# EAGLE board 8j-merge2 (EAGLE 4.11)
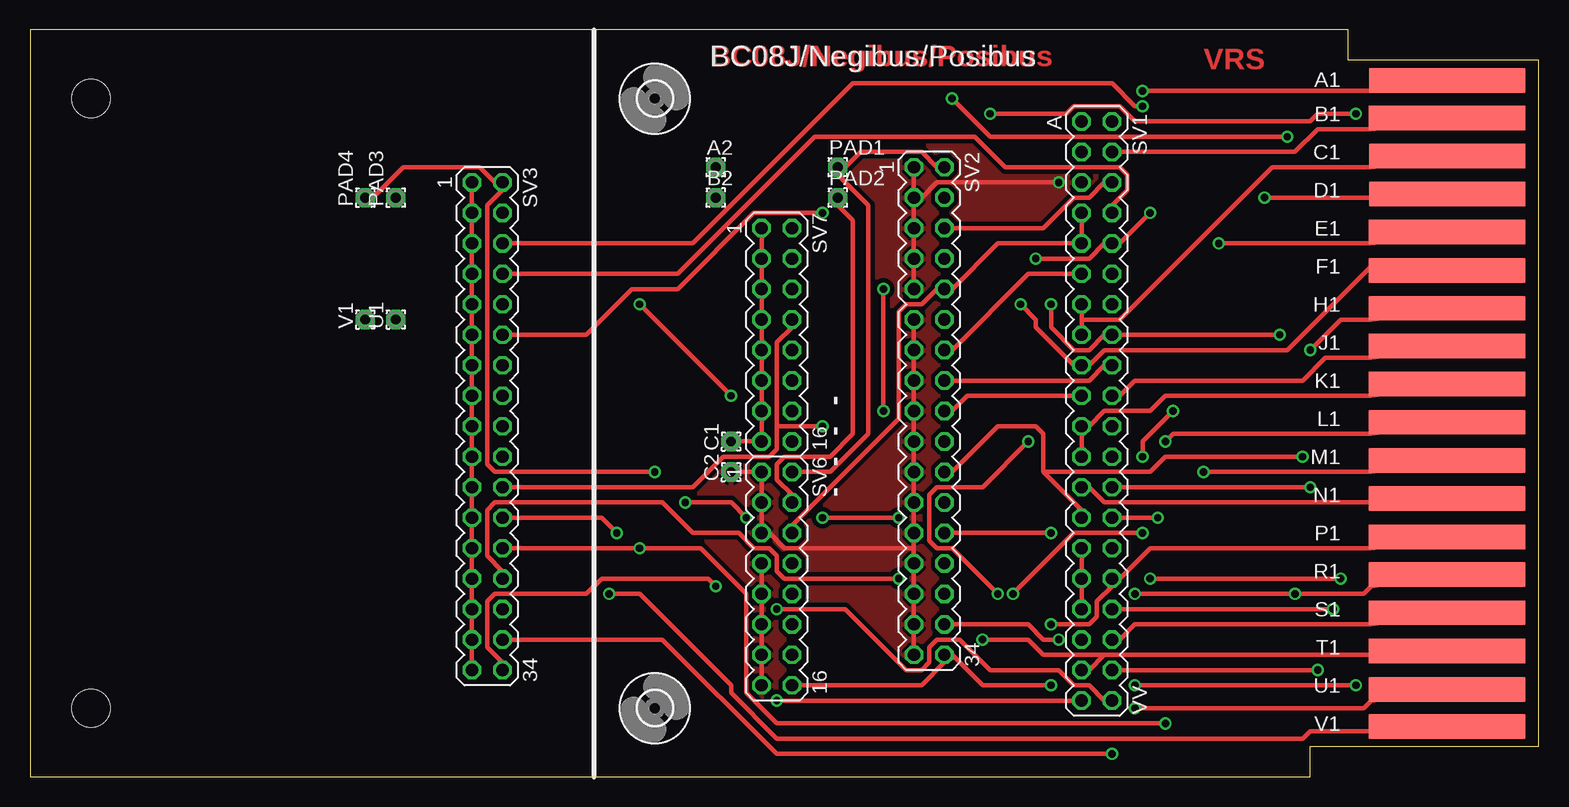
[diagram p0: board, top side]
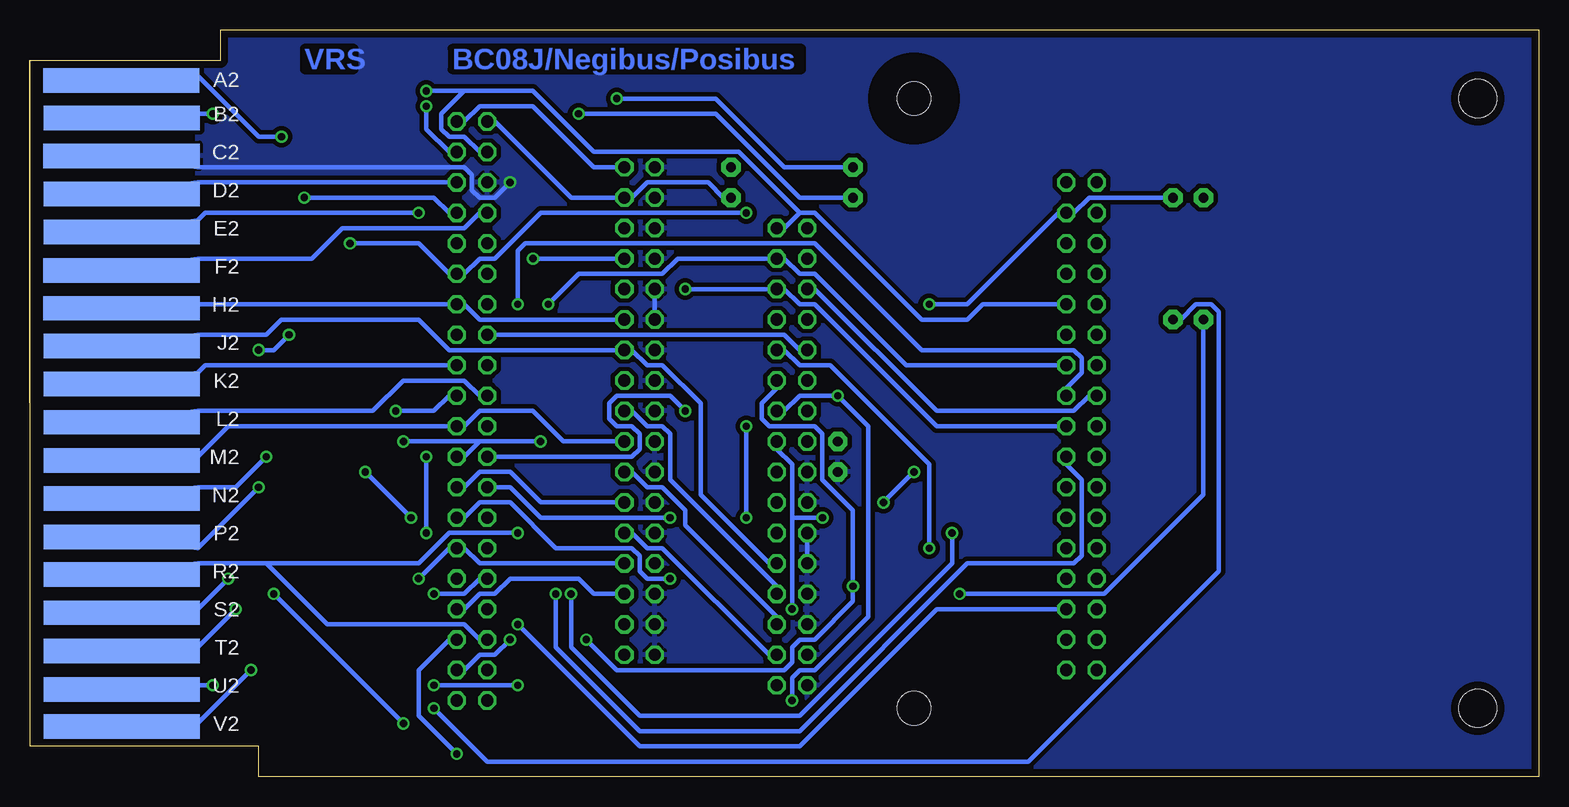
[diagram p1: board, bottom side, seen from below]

Size 125.73 x 62.23 mm. Coordinates in mm from the lower left corner, seen from the top.
Copper layers (1*16): Top 0.035mm / dielectric 1.5mm / Bottom 0.035mm
Design rules "olimex10mil": minimum track width 15mil, minimum drill 24mil, track to track 15mil, track to pad 10mil, pad to pad 10mil, via to via 10mil, smd to smd 10mil, copper to edge 25mil, drill to drill 10mil, minimum pad ring 10mil, minimum via ring 8mil, stop-mask expansion 0mil, vias tented up to drill 0mil, thermal gap 10mil

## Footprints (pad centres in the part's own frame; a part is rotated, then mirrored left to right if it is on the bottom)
1,6/0,8 = drill 0.813 pad 1.6 octagon: 1 0,0
DEC40PINV = drill 1.016 octagon: A -24.13,-1.27; AA 3.81,-1.27; B -24.13,1.27; BB 3.81,1.27; C -21.59,-1.27; CC 6.35,-1.27; D -21.59,1.27; DD 6.35,1.27; E -19.05,-1.27; EE 8.89,-1.27; F -19.05,1.27; FF 8.89,1.27; H -16.51,-1.27; HH 11.43,-1.27; J -16.51,1.27; JJ 11.43,1.27; K -13.97,-1.27; KK 13.97,-1.27; L -13.97,1.27; LL 13.97,1.27; M -11.43,-1.27; MM 16.51,-1.27; N -11.43,1.27; NN 16.51,1.27; P -8.89,-1.27; PP 19.05,-1.27; R -8.89,1.27; RR 19.05,1.27; S -6.35,-1.27; SS 21.59,-1.27; T -6.35,1.27; TT 21.59,1.27; U -3.81,-1.27; UU 24.13,-1.27; V -3.81,1.27; VV 24.13,1.27; W -1.27,-1.27; X -1.27,1.27; Y 1.27,-1.27; Z 1.27,1.27
MA17-2 = drill 1.016 octagon: 1 -20.32,-1.27; 2 -20.32,1.27; 3 -17.78,-1.27; 4 -17.78,1.27; 5 -15.24,-1.27; 6 -15.24,1.27; 7 -12.7,-1.27; 8 -12.7,1.27; 9 -10.16,-1.27; 10 -10.16,1.27; 11 -7.62,-1.27; 12 -7.62,1.27; 13 -5.08,-1.27; 14 -5.08,1.27; 15 -2.54,-1.27; 16 -2.54,1.27; 17 0,-1.27; 18 0,1.27; 19 2.54,-1.27; 20 2.54,1.27; 21 5.08,-1.27; 22 5.08,1.27; 23 7.62,-1.27; 24 7.62,1.27; 25 10.16,-1.27; 26 10.16,1.27; 27 12.7,-1.27; 28 12.7,1.27; 29 15.24,-1.27; 30 15.24,1.27; 31 17.78,-1.27; 32 17.78,1.27; 33 20.32,-1.27; 34 20.32,1.27
MA08-2 = drill 1.016 octagon: 1 -8.89,-1.27; 2 -8.89,1.27; 3 -6.35,-1.27; 4 -6.35,1.27; 5 -3.81,-1.27; 6 -3.81,1.27; 7 -1.27,-1.27; 8 -1.27,1.27; 9 1.27,-1.27; 10 1.27,1.27; 11 3.81,-1.27; 12 3.81,1.27; 13 6.35,-1.27; 14 6.35,1.27; 15 8.89,-1.27; 16 8.89,1.27
SINGLE-R = hole 3.175: 5.08,5.715; 5.08,56.515
EDGE-CON2 = smd 13.017 x 2.032: A1 7.633,4.207; B1 7.639,7.327; C1 7.636,10.489; D1 7.633,13.665; E1 7.642,16.84; F1 7.642,20.041; H1 7.642,23.19; J1 7.642,26.34; K1 7.642,29.515; L1 7.642,32.69; M1 7.642,35.89; N1 7.642,39.04; P1 7.642,42.24; R1 7.642,45.39; S1 7.642,48.565; T1 7.642,51.74; U1 7.642,54.966; V1 7.642,58.026 | smd 13.017 x 2.032 bottom: A2 7.614,4.207; B2 7.642,7.328; C2 7.617,10.49; D2 7.642,13.665; E2 7.642,16.84; F2 7.617,20.041; H2 7.617,23.19; J2 7.642,26.34; K2 7.642,29.515; L2 7.642,32.69; M2 7.642,35.89; N2 7.642,39.04; P2 7.642,42.24; R2 7.642,45.39; S2 7.642,48.565; T2 7.642,51.74; U2 7.642,54.966; V2 7.642,58.026
2,8 = hole 2.8: 0,0

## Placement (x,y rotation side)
A2  [1,6/0,8]  57.15,50.8 0 top
B2  [1,6/0,8]  57.15,48.26 0 top
C1  [1,6/0,8]  58.42,27.94 90 top
C2  [1,6/0,8]  58.42,25.4 90 top
PAD1  [1,6/0,8]  67.31,50.8 0 top
PAD2  [1,6/0,8]  67.31,48.26 0 top
PAD3  [1,6/0,8]  30.48,48.26 90 top
PAD4  [1,6/0,8]  27.94,48.26 90 top
SV1  [DEC40PINV]  88.9,30.48 270 top
SV2  [MA17-2]  74.93,30.48 270 top
SV3  [MA17-2]  38.1,29.21 270 top
SV6  [MA08-2]  62.23,16.51 270 top
SV7  [MA08-2]  62.23,36.83 270 top
U1  [1,6/0,8]  30.48,38.1 90 top
U$1  OUTLINE-SINGLE-R  [SINGLE-R]  0,0 0 top
U$2  [EDGE-CON2]  125.73,62.23 180 top
U$3  [2,8]  52.07,56.52 0 top
U$4  [2,8]  52.07,5.71 0 top
V1  [1,6/0,8]  27.94,38.1 90 top

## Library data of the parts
A2 B2 C1 C2 PAD1-PAD4 U1 V1 = wirepad
SV1 U$1 U$2 = dec-con
SV2 SV3 SV6 SV7 = con-lstb
U$3 U$4 = holes

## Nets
-15V: B2.1 U$2.B2
A1: SV1.C SV3.10 SV7.2 U$2.A1
B1: SV1.D SV3.6 U$2.B1
C1: C1.1 SV1.P SV1.S SV3.1 SV3.3 SV3.5 SV3.7 SV3.9 SV3.11 SV3.13 SV3.15 SV3.17 SV3.19 SV3.21 SV3.23 SV3.25 SV3.27 SV3.29 SV3.31 SV3.33 SV7.1 SV7.3 SV7.5 SV7.7 SV7.9 SV7.11 SV7.13 SV7.15 U$2.C1
C2: C2.1 SV1.E SV2.1 SV2.3 SV2.5 SV2.7 SV2.9 SV2.11 SV2.13 SV2.15 SV2.17 SV2.19 SV2.21 SV2.23 SV2.25 SV2.27 SV2.29 SV2.31 SV2.33 SV6.1 SV6.3 SV6.5 SV6.7 SV6.9 SV6.11 SV6.13 SV6.15 U$2.C2
D1: SV1.J SV3.8 U$2.D1
D2: SV1.F SV2.6 U$2.D2
E1: SV1.N SV3.12 U$2.E1
E2: SV1.L SV2.8 U$2.E2
F1: SV1.U SV3.14 SV7.4 U$2.F1
F2: SV1.H SV1.K SV2.10 SV6.6 U$2.F2
H1: SV1.T SV3.16 U$2.H1
H2: SV1.R SV2.12 U$2.H2
J1: SV1.X SV3.20 U$2.J1
J2: SV1.M SV2.14 SV6.8 U$2.J2
JA2: PAD1.1 SV1.B SV2.2 SV6.2
JB2: PAD2.1 SV1.A SV2.4 SV6.4
JU1: PAD3.1 SV1.UU SV3.4 SV7.14
JV1: PAD4.1 SV1.VV SV3.2 SV7.16
K1: SV1.AA SV1.Y SV3.18 SV7.6 U$2.K1
K2: SV1.V SV2.16 U$2.K2
L1: SV1.BB SV3.24 U$2.L1
L2: SV1.W SV2.18 SV6.10 U$2.L2
M1: SV1.FF SV3.28 U$2.M1
M2: SV1.Z SV2.20 U$2.M2
N1: SV1.CC SV3.22 SV7.8 U$2.N1
N2: SV1.EE SV2.22 SV6.12 U$2.N2
P1: SV1.LL SV3.30 U$2.P1
P2: SV1.DD SV2.24 U$2.P2
R1: SV1.HH SV1.KK SV1.MM SV3.26 SV7.10 U$2.R1
R2: SV1.PP SV2.26 SV6.14 U$2.R2
S1: SV1.RR SV3.32 U$2.S1
S2: SV1.JJ SV2.28 U$2.S2
T1: SV1.SS SV3.34 SV7.12 U$2.T1
T2: SV1.NN SV2.30 U$2.T2
U1: U1.1 U$2.U1
U2: SV2.34 SV6.16 U$2.U2
V1: U$2.V1 V1.1
V2: SV1.TT SV2.32 U$2.V2
VCC: A2.1 U$2.A2

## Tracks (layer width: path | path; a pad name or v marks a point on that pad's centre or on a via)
-15V  (via drill 0.61)
  Top 0.381: v80.01,55.24 86.36,55.24 87,55.88 90.81,55.88 92.08,54.61 106.68,54.61 107.31,55.24 v110.49,55.24
  Bottom 0.381: v80.01,55.24 68.58,55.24 61.59,48.26 57.78,48.26 B2.1 | v110.49,55.24 111.76,55.24 U$2.B2
A1  (via drill 0.61)
  Top 0.381: v92.71,57.15 111.76,57.15 U$2.A1
  Bottom 0.381: 61.59,46.99 60.33,46.99 51.44,38.1 47.62,38.1 46.35,39.37 40.01,39.37 SV3.10 | 61.59,46.99 62.87,45.72 SV7.2 | 89.53,57.15 91.44,55.24 91.44,53.98 90.81,53.34 89.53,53.34 88.27,52.07 SV1.C | 89.53,57.15 83.82,57.15 78.74,52.07 66.67,52.07 61.59,46.99 | 89.53,57.15 v92.71,57.15
B1  (via drill 0.61)
  Top 0.381: v92.71,55.88 92.08,55.88 90.17,57.78 68.58,57.78 55.24,44.45 40.01,44.45 SV3.6 | U$2.B1 111.76,53.98 107.31,53.98 105.41,52.07 90.81,52.07 SV1.D
  Bottom 0.381: v92.71,55.88 92.71,53.98 90.81,52.07 SV1.D
C1
  Top 0.381: SV3.33 36.83,9.53 36.83,10.79 SV3.31 36.83,12.06 36.83,13.34 SV3.29 36.83,14.61 36.83,15.88 SV3.27 36.83,17.14 36.83,18.41 SV3.25 36.83,19.68 36.83,20.95 SV3.23 36.83,22.23 36.83,23.5 SV3.21 36.83,24.77 36.83,26.04 SV3.19 36.83,27.3 36.83,28.57 SV3.17 36.83,29.84 36.83,31.11 SV3.15 36.83,32.38 36.83,33.66 SV3.13 36.83,34.92 36.83,36.2 SV3.11 36.83,37.47 36.83,38.73 SV3.9 36.83,40.01 36.83,41.27 SV3.7 36.83,42.55 36.83,43.81 SV3.5 36.83,45.09 36.83,46.35 SV3.3 36.83,47.62 36.83,48.9 SV3.1 | 87.63,38.1 87.63,38.73 SV1.P | 87.63,38.1 87.63,37.47 SV1.S | C1.1 59.05,27.94 60.33,27.94 SV7.15 60.96,28.57 60.96,29.84 SV7.13 60.96,31.11 60.96,32.38 SV7.11 60.96,33.66 60.96,34.92 SV7.9 60.96,36.2 60.96,37.47 SV7.7 60.96,38.73 60.96,40.01 SV7.5 60.96,41.27 60.96,42.55 SV7.3 60.96,43.81 60.96,45.09 SV7.1 | 87.63,38.1 90.81,38.1 103.5,50.8 111.76,50.8 U$2.C1
  Bottom 0.381: SV1.S 87,36.83 62.87,36.83 61.59,35.56 SV7.9 | SV3.15 37.47,31.75 38.73,30.48 50.16,30.48 60.33,40.64 SV7.5
C2  (via drill 0.61)
  Top 0.381: SV6.15 60.96,8.26 60.96,9.53 SV6.13 60.96,10.79 60.96,12.06 SV6.11 60.96,13.34 60.96,14.61 SV6.9 60.96,15.88 60.96,17.14 SV6.7 | C2.1 59.05,25.4 60.33,25.4 SV6.1 60.96,24.77 60.96,23.5 SV6.3 60.96,22.23 60.96,20.95 SV6.5 61.59,20.32 62.87,19.05 73.66,19.05 | SV2.33 73.66,10.79 73.66,12.06 SV2.31 73.66,13.34 73.66,14.61 SV2.29 73.66,15.88 73.66,17.14 SV2.27 73.66,18.41 73.66,19.05 | 73.66,19.05 73.66,19.68 SV2.25 73.66,20.95 73.66,22.23 SV2.23 73.66,23.5 73.66,24.77 SV2.21 73.66,26.04 73.66,27.3 SV2.19 73.66,28.57 73.66,29.84 SV2.17 73.66,31.11 73.66,32.38 SV2.15 73.66,33.66 73.66,34.92 SV2.13 73.66,36.2 73.66,37.47 SV2.11 | SV2.9 73.66,41.27 73.66,42.55 SV2.7 73.66,43.81 73.66,45.09 SV2.5 73.66,46.35 73.66,47.62 SV2.3 | SV2.1 73.66,50.16 73.66,48.9 SV2.3 | v85.72,49.53 75.56,49.53 74.3,48.26 SV2.3
  Bottom 0.381: SV6.5 60.96,19.68 60.96,18.41 SV6.7 | SV2.9 73.66,40.01 73.66,38.73 SV2.11 | v85.72,49.53 87,48.26 88.27,48.26 88.9,48.9 88.9,50.16 89.53,50.8 111.76,50.8 U$2.C2
  pour Bottom (isolate 0.254): 0,0 111.76,0 111.76,62.23 0,62.23
  pour Top (isolate 0.254): 0,0 111.76,0 111.76,62.23 0,62.23
D1  (via drill 0.61)
  Top 0.381: SV3.8 40.01,41.91 53.98,41.91 65.41,53.34 78.74,53.34 81.28,50.8 90.81,50.8 91.44,50.16 91.44,48.9 90.17,47.62 SV1.J | v102.87,48.26 111.76,48.26 U$2.D1
  Bottom 0.381: v102.87,48.26 92.08,48.26 90.81,46.99 SV1.J
D2
  Top 0.381: SV2.6 76.83,45.72 84.45,45.72 87,48.26 88.27,48.26 89.53,49.53 SV1.F
  Bottom 0.381: SV1.F 90.81,49.53 111.76,49.53 U$2.D2
E1  (via drill 0.61)
  Top 0.381: v66.04,46.99 60.33,46.99 53.98,40.64 50.16,40.64 46.35,36.83 40.01,36.83 SV3.12 | v99.06,44.45 111.76,44.45 U$2.E1
  Bottom 0.381: v66.04,46.99 83.19,46.99 87,43.18 88.27,43.18 89.53,41.91 SV1.N 90.81,41.91 93.34,44.45 v99.06,44.45
E2  (via drill 0.61)
  Top 0.381: v83.82,43.18 88.27,43.18 89.53,44.45 SV1.L 90.81,44.45 v93.34,46.99
  Bottom 0.381: v83.82,43.18 76.83,43.18 SV2.8 | v93.34,46.99 111.12,46.99 111.76,46.35 U$2.E2
F1  (via drill 0.61)
  Top 0.381: U$2.F1 111.76,42.55 104.78,35.56 89.53,35.56 88.27,34.29 SV1.U 87,34.29 83.82,37.47 83.82,38.1 v82.55,39.37
  Bottom 0.381: SV3.14 40.01,34.29 52.7,34.29 60.33,41.91 61.59,41.91 62.87,43.18 SV7.4 64.14,43.18 71.75,43.18 73.03,41.91 80.01,41.91 v82.55,39.37
F2
  Top 0.381: SV1.H 87.63,46.35 87.63,45.09 SV1.K 87,44.45 80.64,44.45 76.83,40.64 SV2.10 75.56,40.64 74.3,39.37 73.03,39.37 72.39,38.73 72.39,29.84 63.5,20.95 SV6.6
  Bottom 0.381: U$2.F2 111.76,43.18 102.23,43.18 99.69,45.72 89.53,45.72 88.27,46.99 SV1.H
H1  (via drill 0.61)
  Top 0.381: v85.09,39.37 85.09,37.47 87,35.56 88.27,35.56 89.53,36.83 SV1.T 90.81,36.83 v104.14,36.83 | v106.68,35.56 109.22,38.1 111.76,38.1 U$2.H1
  Bottom 0.381: v85.09,39.37 85.09,43.81 84.45,44.45 60.33,44.45 51.44,35.56 38.73,35.56 38.1,34.92 38.1,33.66 39.37,32.38 SV3.16 | v106.68,35.56 105.41,35.56 v104.14,36.83
H2
  Bottom 0.381: SV2.12 76.83,38.1 88.27,38.1 89.53,39.37 SV1.R 90.81,39.37 111.76,39.37 U$2.H2
J1  (via drill 0.61)
  Top 0.381: v81.92,15.24 87,20.32 v92.71,20.32 | v92.71,26.67 92.71,27.94 v95.25,30.48 | U$2.J1 111.76,34.92 107.95,34.92 106.05,33.02 92.08,33.02 90.81,31.75 SV1.X
  Bottom 0.381: v81.92,15.24 81.92,10.79 74.93,3.81 61.59,3.81 47.62,17.78 38.73,17.78 38.1,18.41 38.1,24.77 39.37,26.04 SV3.20 | v92.71,20.32 v92.71,26.67 | v95.25,30.48 92.08,30.48 90.81,31.75 SV1.X
J2
  Top 0.381: SV1.M 87,41.91 83.19,41.91 76.83,35.56 SV2.14
  Bottom 0.381: SV6.8 64.14,17.78 69.85,23.5 69.85,31.11 73.03,34.29 74.3,34.29 75.56,35.56 SV2.14 76.83,35.56 90.81,35.56 93.34,38.1 104.78,38.1 106.05,36.83 111.76,36.83 U$2.J2
JA2
  Top 0.381: SV6.2 64.14,25.4 66.67,25.4 69.85,28.57 69.85,47.62 67.31,50.16 PAD1.1 67.94,50.8 69.22,52.07 74.3,52.07 75.56,50.8 SV2.2
  Bottom 0.381: SV1.B 89.53,54.61 88.27,55.88 83.82,55.88 78.74,50.8 76.83,50.8 SV2.2
JB2
  Top 0.381: SV6.4 63.5,23.5 62.23,24.77 62.23,26.04 62.87,26.67 66.67,26.67 68.58,28.57 68.58,46.35 67.31,47.62 PAD2.1
  Bottom 0.381: SV1.A 87,54.61 80.64,48.26 76.83,48.26 SV2.4 75.56,48.26 74.3,49.53 69.22,49.53 67.94,48.26 PAD2.1
JU1  (via drill 0.61)
  Top 0.381: v58.42,31.75 v50.8,39.37 | v62.23,6.35 87,6.35 SV1.UU
  Bottom 0.381: v50.8,39.37 47.62,39.37 40.01,46.99 SV3.4 38.73,46.99 37.47,48.26 31.11,48.26 PAD3.1 | SV7.14 62.87,30.48 61.59,31.75 v58.42,31.75 55.88,29.21 55.88,13.34 60.33,8.89 61.59,8.89 62.23,8.26 v62.23,6.35
JV1  (via drill 0.61)
  Top 0.381: PAD4.1 28.57,48.26 31.11,50.8 37.47,50.8 38.73,49.53 SV3.2 39.37,48.9 38.1,47.62 38.1,26.04 38.73,25.4 v52.07,25.4 | v62.23,13.97 67.94,13.97 73.03,8.89 74.3,8.89 74.93,9.53 74.93,10.79 75.56,11.43 77.47,11.43 80.01,8.89 85.72,8.89 87,7.62 88.27,7.62 89.53,6.35 SV1.VV | v54.61,22.86 58.42,22.86 v59.69,21.59
  Bottom 0.381: 62.23,21.59 v62.23,13.97 | 62.23,21.59 62.23,26.04 63.5,27.3 SV7.16 | v52.07,25.4 v54.61,22.86 | v59.69,21.59 62.23,21.59
K1  (via drill 0.61)
  Top 0.381: SV1.AA 87.63,27.3 87.63,28.57 SV1.Y 88.27,29.21 89.53,30.48 93.34,30.48 94.61,31.75 111.76,31.75 U$2.K1 | v71.12,40.64 v71.12,30.48
  Bottom 0.381: SV3.18 40.01,29.21 50.16,29.21 60.33,39.37 61.59,39.37 62.87,40.64 SV7.6 64.14,40.64 v71.12,40.64 | v71.12,30.48 72.39,31.75 76.83,31.75 77.47,31.11 77.47,29.84 76.83,29.21 75.56,29.21 74.93,28.57 74.93,27.3 75.56,26.67 87,26.67 SV1.AA
K2
  Top 0.381: SV2.16 76.83,33.02 88.27,33.02 89.53,34.29 SV1.V
  Bottom 0.381: SV1.V 90.81,34.29 111.12,34.29 111.76,33.66 U$2.K2
L1  (via drill 0.61)
  Top 0.381: v48.9,20.32 47.62,21.59 40.01,21.59 SV3.24 | v80.64,15.24 76.83,19.05 75.56,19.05 74.93,19.68 74.93,23.5 75.56,24.13 79.38,24.13 v83.19,27.94 | v94.61,27.94 95.25,28.57 111.76,28.57 U$2.L1
  Bottom 0.381: v48.9,20.32 48.9,17.78 61.59,5.08 74.93,5.08 80.64,10.79 v80.64,15.24 | v83.19,27.94 88.27,27.94 | 88.27,27.94 89.53,26.67 SV1.BB | 88.27,27.94 v94.61,27.94
L2
  Top 0.381: SV1.W 87,31.75 78.11,31.75 76.83,30.48 SV2.18
  Bottom 0.381: SV6.10 63.5,15.88 72.39,24.77 72.39,28.57 73.03,29.21 74.3,29.21 75.56,30.48 SV2.18 | U$2.L2 111.76,30.48 97.16,30.48 94.61,33.02 89.53,33.02 88.27,31.75 SV1.W
M1  (via drill 0.61)
  Top 0.381: v72.39,16.51 62.87,16.51 62.23,17.14 62.23,18.41 61.59,19.05 60.33,19.05 59.05,20.32 55.24,20.32 52.7,22.86 38.73,22.86 38.1,22.23 38.1,18.41 39.37,17.14 SV3.28 | v97.79,25.4 111.76,25.4 U$2.M1 | v93.98,21.59 90.81,21.59 SV1.FF
  Bottom 0.381: v72.39,16.51 74.3,16.51 74.93,17.14 74.93,18.41 75.56,19.05 81.92,19.05 85.72,22.86 88.27,22.86 89.53,21.59 SV1.FF | v93.98,21.59 v97.79,25.4
M2
  Bottom 0.381: SV2.20 76.83,27.94 81.28,27.94 83.82,30.48 88.27,30.48 89.53,29.21 SV1.Z 90.81,29.21 109.22,29.21 111.76,26.67 U$2.M2
N1  (via drill 0.61)
  Top 0.381: 62.23,29.21 62.23,36.2 63.5,37.47 SV7.8 | 62.23,29.21 62.23,27.3 61.59,26.67 57.78,26.67 55.24,24.13 40.01,24.13 SV3.22 | SV1.CC 88.27,24.13 89.53,22.86 111.76,22.86 U$2.N1 | 62.23,29.21 v66.04,29.21 | v66.04,21.59 v72.39,21.59
  Bottom 0.381: v66.04,29.21 v66.04,21.59 | v72.39,21.59 83.19,21.59 85.72,24.13 87,24.13 SV1.CC
N2  (via drill 0.61)
  Top 0.381: 84.45,25.4 87.63,22.23 SV1.EE | 84.45,25.4 84.45,28.57 83.82,29.21 80.64,29.21 76.83,25.4 SV2.22 | v106.05,26.67 94.61,26.67 93.34,25.4 84.45,25.4
  Bottom 0.381: SV6.12 63.5,13.34 71.12,20.95 71.12,22.23 73.03,24.13 74.3,24.13 75.56,25.4 SV2.22 | v106.05,26.67 108.58,24.13 111.76,24.13 U$2.N2
P1  (via drill 0.61)
  Top 0.381: v85.09,12.7 88.27,12.7 88.9,13.34 88.9,14.61 90.17,15.88 SV1.LL 90.81,16.51 93.34,19.05 111.76,19.05 U$2.P1
  Bottom 0.381: v85.09,12.7 74.93,2.54 61.59,2.54 50.16,13.97 40.01,13.97 SV3.30
P2  (via drill 0.61)
  Top 0.381: v106.68,24.13 90.81,24.13 SV1.DD
  Bottom 0.381: SV2.24 76.83,22.86 83.19,22.86 85.72,25.4 88.27,25.4 89.53,24.13 SV1.DD | v106.68,24.13 111.76,19.05 U$2.P2
R1  (via drill 0.61)
  Top 0.381: SV1.MM 87.63,14.61 87.63,15.88 SV1.KK 87.63,17.14 87.63,18.41 SV1.HH | v92.08,15.24 v105.41,15.24 111.12,15.24 111.76,15.88 U$2.R1 | v94.61,4.45 62.23,4.45 59.69,6.99 59.69,15.24 55.88,19.05 v50.8,19.05 40.01,19.05 SV3.26
  Bottom 0.381: v92.08,15.24 89.53,15.24 88.27,16.51 SV1.KK | v94.61,4.45 v105.41,15.24 | v50.8,19.05 50.8,26.04 59.05,34.29 61.59,34.29 62.87,35.56 SV7.10
R2  (via drill 0.61)
  Top 0.381: v85.09,20.32 76.83,20.32 SV2.26
  Bottom 0.381: SV6.14 64.14,10.16 73.03,19.05 74.3,19.05 75.56,20.32 SV2.26 | 106.05,17.78 100.97,12.7 89.53,12.7 88.27,11.43 SV1.PP | 106.05,17.78 111.76,17.78 U$2.R2 | v85.09,20.32 90.81,20.32 93.34,17.78 106.05,17.78
S1  (via drill 0.61)
  Top 0.381: v90.17,1.91 62.23,1.91 52.7,11.43 40.01,11.43 SV3.32 | U$2.S1 111.76,12.7 92.08,12.7 90.81,11.43 SV1.RR
  Bottom 0.381: v90.17,1.91 93.34,5.08 93.34,8.89 90.81,11.43 SV1.RR
S2  (via drill 0.61)
  Top 0.381: v93.34,16.51 v109.22,16.51
  Bottom 0.381: SV2.28 76.83,17.78 88.27,17.78 89.53,19.05 SV1.JJ 90.81,19.05 v93.34,16.51 | v109.22,16.51 111.76,13.97 U$2.S2
T1  (via drill 0.61)
  Top 0.381: v57.15,15.88 56.52,16.51 47.62,16.51 46.35,15.24 38.73,15.24 38.1,14.61 38.1,10.79 39.37,9.53 SV3.34 | 89.53,10.16 88.27,8.89 SV1.SS | 89.53,10.16 111.76,10.16 U$2.T1 | v79.38,11.43 83.19,11.43 84.45,10.16 89.53,10.16
  Bottom 0.381: SV7.12 63.5,32.38 64.77,31.11 64.77,29.84 64.14,29.21 60.33,29.21 59.69,28.57 59.69,24.77 57.15,22.23 v57.15,15.88 57.15,14.61 60.33,11.43 61.59,11.43 62.23,10.79 62.23,9.53 62.87,8.89 76.83,8.89 v79.38,11.43
T2  (via drill 0.61)
  Top 0.381: v108.58,13.97 90.81,13.97 SV1.NN
  Bottom 0.381: SV2.30 76.83,15.24 78.74,15.24 80.01,16.51 85.72,16.51 87,15.24 88.27,15.24 89.53,13.97 SV1.NN | v108.58,13.97 111.76,10.79 U$2.T2
U1  (via drill 0.61)
  Top 0.381: v92.08,5.71 111.12,5.71 111.76,6.35 U$2.U1
  Bottom 0.381: v92.08,5.71 87.63,1.27 42.55,1.27 26.67,17.14 26.67,38.73 27.3,39.37 28.57,39.37 29.84,38.1 U1.1
U2  (via drill 0.61)
  Top 0.381: SV6.16 64.14,7.62 74.3,7.62 76.2,9.53 SV2.34 76.83,10.16 79.38,7.62 v85.09,7.62 | v92.08,7.62 v110.49,7.62
  Bottom 0.381: v85.09,7.62 v92.08,7.62 | v110.49,7.62 111.76,7.62 U$2.U2
V1  (via drill 0.61)
  Top 0.381: v48.26,15.24 50.8,15.24 58.42,7.62 58.42,6.99 62.23,3.17 106.05,3.17 106.68,3.81 111.76,3.81 U$2.V1
  Bottom 0.381: v48.26,15.24 36.2,15.24 27.94,23.5 27.94,37.47 V1.1
V2  (via drill 0.61)
  Top 0.381: v107.31,8.89 90.81,8.89 SV1.TT | v85.72,11.43 84.45,11.43 83.19,12.7 76.83,12.7 SV2.32
  Bottom 0.381: v107.31,8.89 111.76,4.45 U$2.V2 | v85.72,11.43 87,10.16 88.27,10.16 89.53,8.89 SV1.TT
VCC  (via drill 0.61)
  Top 0.381: v76.83,56.52 80.01,53.34 v104.78,53.34
  Bottom 0.381: v76.83,56.52 68.58,56.52 62.87,50.8 57.78,50.8 A2.1 | v104.78,53.34 106.68,53.34 111.76,58.42 U$2.A2

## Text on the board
Top: BC08J/Negibus/Posibus | VRS
Bottom: BC08J/Negibus/Posibus | VRS
tPlace: BC08J/Negibus/Posibus | - | - | - | -
tValues: * | * | * | * | * | * | * | * | * | * | * | * | Side 1 | Side 2 | * | * | * | * | * | * | * | BC08J | * | * | * | * | * | * | * | * | * | * | * | * | * | * | * | * | *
